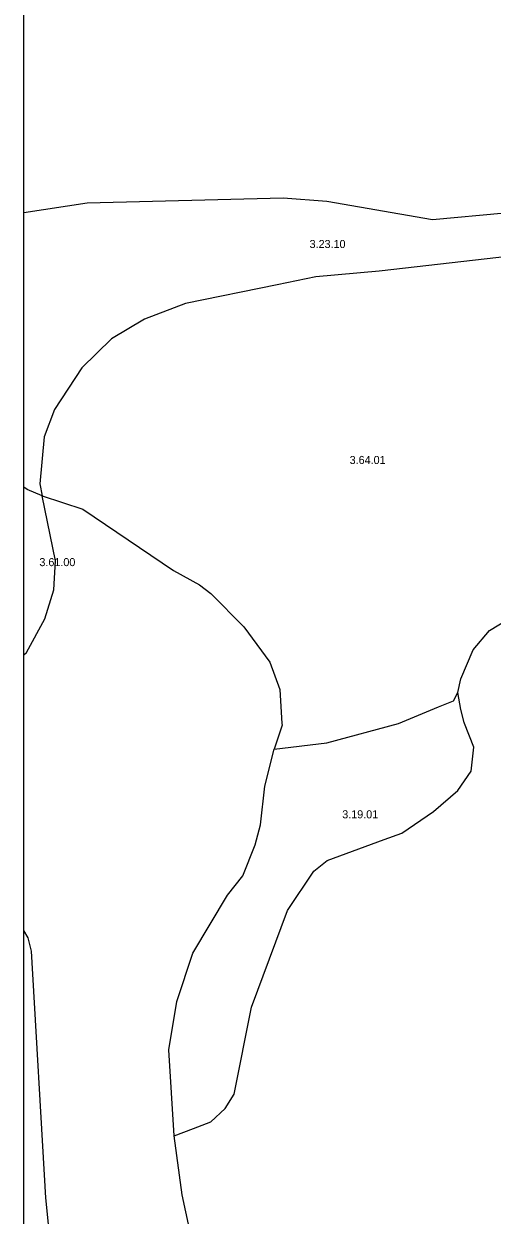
# Model space of a CAD drawing. Extents: x -662500 to -655523, y -1056000 to -1049993.
# Drawn here: x -662500 to -662064, y -1052458 to -1051349 of the extents above; entities that cross this region are included whole.
import ezdxf

# ---------------------------------------------------------------- set-up
doc = ezdxf.new("R2010")
doc.units = 0
doc.layers.add('Vrstva 24', color=7, linetype='Continuous')

msp = doc.modelspace()

# ---------------------------------------------------------------- linework, layer by layer
at = {"layer": 'Vrstva 24'}
for points in [[(-662500, -1051524.6), (-662500, -1051215.9)], [(-661951, -1051594.5), (-661961.5, -1051566), (-661974, -1051548), (-661994.5, -1051533.5), (-662011.5, -1051527.5), (-662052, -1051525), (-662119.5, -1051531), (-662218, -1051514), (-662258.5, -1051511), (-662441, -1051515.5), (-662500, -1051524.6)], [(-662500, -1051780.1), (-662500, -1051524.6)], [(-661951, -1051594.5), (-661973, -1051578), (-661983.5, -1051572.5), (-662004, -1051565.5), (-662036, -1051563.5), (-662169, -1051579), (-662228, -1051584), (-662264, -1051591.5), (-662349.5, -1051609), (-662387.5, -1051623.5), (-662418.5, -1051642), (-662446, -1051669), (-662471.5, -1051707.5), (-662481, -1051733), (-662485, -1051777), (-662483, -1051788)], [(-662483, -1051788), (-662497, -1051782), (-662500, -1051780.1)], [(-662500, -1051936.2), (-662500, -1051780.1)], [(-662500, -1051936.2), (-662497.5, -1051934), (-662480.5, -1051902.5), (-662472, -1051875.5), (-662470.5, -1051848.5), (-662483, -1051788)], [(-662483, -1051788), (-662445, -1051800.5), (-662360.5, -1051857.5), (-662336.5, -1051871), (-662326, -1051879), (-662295, -1051910), (-662271, -1051943), (-662261.5, -1051968.5), (-662259.6, -1052000), (-662259.5, -1052001.5), (-662267, -1052024)], [(-662096, -1051971), (-662093, -1051958.5), (-662081.5, -1051931.5), (-662066.5, -1051913.5), (-661997.5, -1051871.5), (-661971, -1051851), (-661958.5, -1051841.5), (-661947, -1051823.5), (-661932.5, -1051805), (-661921, -1051803)], [(-662500, -1052192.7), (-662500, -1052000), (-662500, -1051936.2)], [(-662360, -1052384), (-662342, -1052377), (-662326, -1052371), (-662312.5, -1052358.5), (-662304, -1052345), (-662288, -1052264), (-662254.5, -1052174), (-662230, -1052137.5), (-662217.5, -1052127.5), (-662164.5, -1052108), (-662148, -1052102), (-662118.5, -1052082), (-662096, -1052062.5), (-662083.5, -1052044.5), (-662081, -1052022), (-662089.6, -1052000), (-662090, -1051999), (-662093, -1051987), (-662096, -1051971)], [(-662267, -1052024), (-662218, -1052018), (-662151, -1052000), (-662114, -1051984.5), (-662100, -1051979), (-662096, -1051971)], [(-662360, -1052384), (-662365, -1052304), (-662357.5, -1052259), (-662342.5, -1052214), (-662310.5, -1052160), (-662296, -1052142), (-662284.5, -1052113), (-662279.5, -1052094.5), (-662275.5, -1052058.5), (-662267, -1052024)], [(-662500, -1053023.2), (-662500, -1052192.7)], [(-662500, -1053023.2), (-662494, -1053019.5), (-662486, -1053013), (-662479, -1053003.5), (-662475.3, -1053000), (-662456, -1052963.5), (-662427.5, -1052931), (-662414, -1052914), (-662397, -1052886.5), (-662363.5, -1052819.5), (-662359, -1052792.5), (-662358, -1052778), (-662363.5, -1052765.5), (-662367, -1052750), (-662379, -1052727.5), (-662402, -1052683), (-662420.5, -1052657), (-662458, -1052585.5), (-662468.5, -1052549.5), (-662479.5, -1052441.5), (-662493, -1052212), (-662496, -1052199.5), (-662500, -1052192.7)], [(-662248, -1052747), (-662248.5, -1052736.5), (-662258.5, -1052696), (-662291, -1052621), (-662311.5, -1052588), (-662333, -1052529.5), (-662352.5, -1052439), (-662360, -1052384)]]:
    msp.add_lwpolyline(points, dxfattribs=at)

# ---------------------------------------------------------------- texts
for s, p in [('3.23.10', (-662233.9, -1051557.3)), ('3.64.01', (-662196.6, -1051758.4)), ('3.61.00', (-662485.5, -1051853.5)), ('3.19.01', (-662203.5, -1052088.3))]:
    msp.add_text(s, height=7.5, dxfattribs=at).set_placement(p)

doc.saveas('drawing.dxf')
